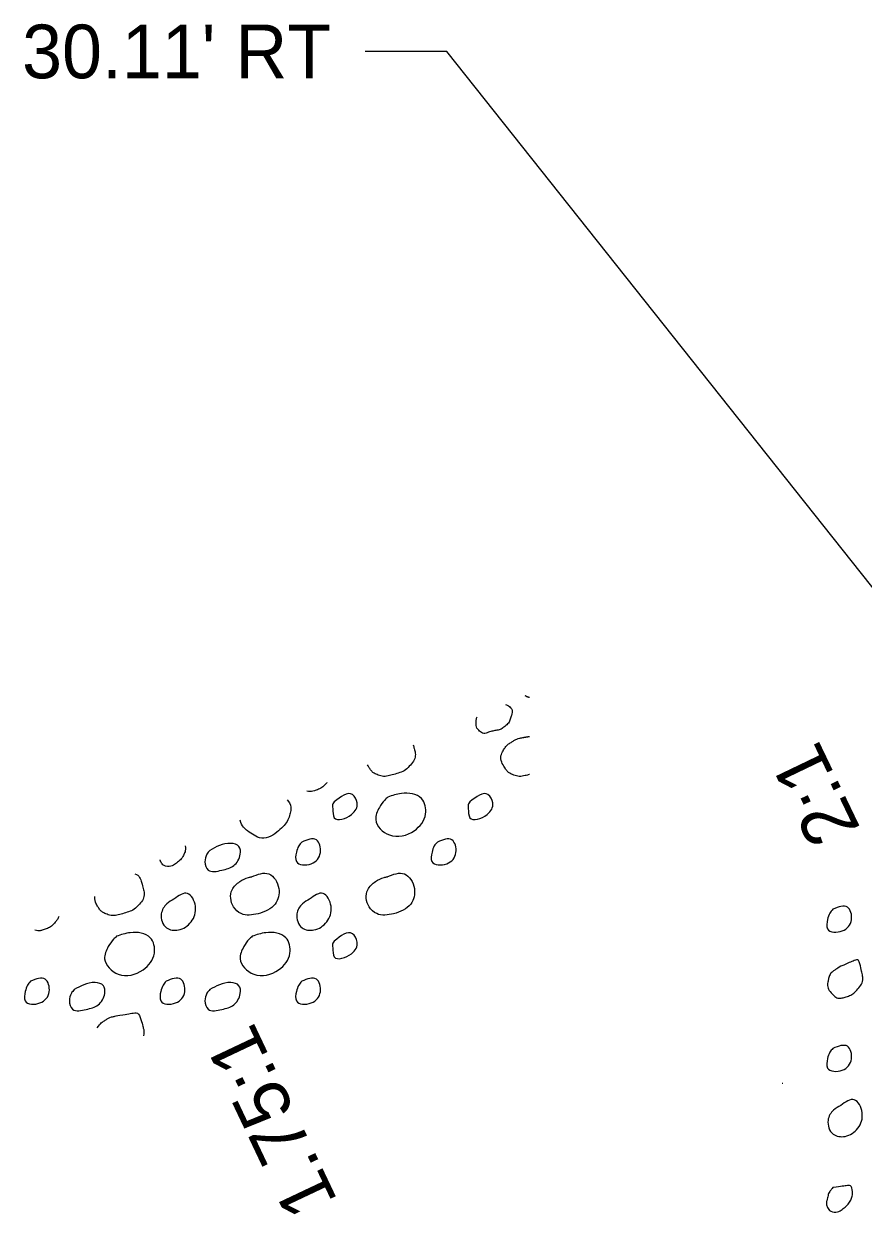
# Model space of a CAD drawing. Extents: x 0 to 2278, y -264 to 330.
# Drawn here: x 81.23 to 114.06, y 222.03 to 268.6 of the extents above; entities that cross this region are included whole.
import ezdxf

# ---------------------------------------------------------------- set-up
doc = ezdxf.new("R2010")
doc.units = 0
doc.layers.add('DR_P_Culvert', color=7, linetype='Continuous')
doc.layers.add('XS_P_Finished_Grade', color=7, linetype='Continuous')

msp = doc.modelspace()

# ---------------------------------------------------------------- linework, layer by layer
at = {"layer": 'DR_P_Culvert'}
for p, q in [((97.773, 267.515), (94.583, 267.515)), ((131.975, 224.45), (97.773, 267.515))]:
    msp.add_line(p, q, dxfattribs=at)
at = {"layer": 'XS_P_Finished_Grade'}
for points, degree in [([(101.009, 242.239), (100.95, 242.252), (100.894, 242.274), (100.84, 242.304)], 2), ([(100.066, 241.966), (100.13, 241.95), (100.192, 241.917), (100.252, 241.857), (100.343, 241.767), (100.33, 241.647), (100.303, 241.552), (100.259, 241.395), (100.2, 241.235), (100.047, 241.107), (99.897, 240.983), (99.738, 240.965), (99.577, 240.927), (99.408, 240.888), (99.215, 240.788), (99.05, 240.936), (98.941, 241.034), (98.918, 241.148), (98.921, 241.26), (98.923, 241.331), (98.93, 241.411), (98.956, 241.481)], 3), ([(96.456, 240.39), (96.476, 240.327), (96.492, 240.266), (96.506, 240.215), (96.558, 240.022), (96.524, 239.786), (96.361, 239.605), (96.161, 239.384), (95.939, 239.299), (95.692, 239.226), (95.48, 239.164), (95.243, 239.141), (95.032, 239.23), (94.904, 239.284), (94.811, 239.377), (94.734, 239.497), (94.71, 239.533), (94.69, 239.572), (94.673, 239.612)], 3), ([(101.009, 239.23), (101.005, 239.229), (101, 239.228), (100.996, 239.226), (100.784, 239.164), (100.547, 239.141), (100.336, 239.23), (100.208, 239.284), (100.115, 239.377), (100.037, 239.497), (99.908, 239.698), (99.869, 239.975), (99.982, 240.165), (100.057, 240.291), (100.159, 240.402), (100.29, 240.485), (100.4, 240.555), (100.506, 240.622), (100.628, 240.647), (100.67, 240.656), (100.711, 240.665), (100.752, 240.674)], 3), ([(100.74, 240.671), (100.829, 240.687), (100.919, 240.703), (101.009, 240.718)], 2), ([(93.085, 238.918), (93.083, 238.915), (93.08, 238.912), (93.077, 238.909), (92.928, 238.729), (92.757, 238.644), (92.577, 238.59), (92.492, 238.564), (92.393, 238.551), (92.297, 238.574)], 3), ([(91.529, 238.239), (91.682, 238.073), (91.688, 237.852), (91.64, 237.682), (91.572, 237.448), (91.424, 237.225), (91.196, 237.03), (90.911, 236.787), (90.515, 236.691), (90.224, 236.864), (89.994, 236.999), (89.753, 237.201), (89.697, 237.439)], 3), ([(87.539, 236.442), (87.554, 236.345), (87.548, 236.239), (87.525, 236.176), (87.465, 236.013), (87.318, 235.851), (87.165, 235.734), (87.008, 235.614), (86.676, 235.634), (86.585, 235.819), (86.573, 235.843), (86.565, 235.867), (86.56, 235.892)], 3), ([(85.572, 235.337), (85.756, 235.298), (85.847, 234.962), (85.899, 234.769), (85.95, 234.576), (85.917, 234.34), (85.754, 234.159), (85.554, 233.938), (85.331, 233.853), (85.085, 233.781), (84.873, 233.718), (84.636, 233.695), (84.425, 233.784), (84.297, 233.838), (84.204, 233.932), (84.126, 234.052), (84.049, 234.171), (84.004, 234.318), (84.004, 234.457)], 3), ([(82.595, 233.667), (82.566, 233.597), (82.524, 233.528), (82.47, 233.463), (82.32, 233.284), (82.15, 233.199), (81.97, 233.144), (81.874, 233.115), (81.761, 233.102), (81.655, 233.139)], 3), ([(113.183, 231.723), (113.358, 231.799), (113.534, 231.874), (113.71, 231.95), (113.892, 232.028), (113.981, 231.628), (114.021, 231.442), (114.064, 231.246), (114.013, 231.025), (113.854, 230.835), (113.704, 230.655), (113.534, 230.57), (113.354, 230.516), (113.21, 230.472), (113.029, 230.465), (112.888, 230.605), (112.717, 230.773), (112.653, 230.972), (112.688, 231.143), (112.715, 231.28), (112.779, 231.46), (112.906, 231.545), (112.998, 231.606), (113.091, 231.664), (113.183, 231.723)], 3), ([(84.098, 229.317), (84.17, 229.425), (84.263, 229.52), (84.379, 229.594), (84.489, 229.664), (84.595, 229.73), (84.717, 229.756), (84.759, 229.765), (84.8, 229.774), (84.841, 229.782)], 3), ([(84.829, 229.78), (85.055, 229.819), (85.283, 229.862), (85.51, 229.894), (85.737, 229.925), (85.842, 229.536), (85.899, 229.324), (85.925, 229.225), (85.929, 229.114), (85.905, 229.006)], 3), ([(110.888, 227.147), (110.899, 227.149), (110.91, 227.152), (110.921, 227.154)], 2), ([(112.876, 223.064), (113.067, 223.092), (113.258, 223.122), (113.449, 223.148), (113.619, 223.171), (113.659, 222.803), (113.605, 222.656), (113.546, 222.493), (113.398, 222.331), (113.245, 222.214), (113.088, 222.094), (112.756, 222.114), (112.665, 222.299), (112.608, 222.416), (112.636, 222.551), (112.669, 222.668), (112.692, 222.751), (112.702, 222.845), (112.756, 222.913), (112.796, 222.964), (112.836, 223.014), (112.876, 223.064)], 3)]:
    msp.add_open_spline(points, degree=degree, dxfattribs=at)
for points in [[(93.369, 238.155), (94.081, 238.444), (94.27, 238.116), (94.046, 237.662), (93.371, 237.536), (93.312, 237.896), (93.319, 238.077), (93.369, 238.155)], [(95.467, 238.344), (96.001, 238.484), (96.782, 238.286), (96.944, 237.682), (96.5, 237.03), (95.527, 236.864), (94.996, 237.461), (95.139, 237.939), (95.346, 238.227), (95.467, 238.344)], [(98.672, 238.155), (99.385, 238.444), (99.573, 238.116), (99.35, 237.662), (98.675, 237.536), (98.616, 237.896), (98.622, 238.077), (98.672, 238.155)], [(92.1, 236.584), (92.672, 236.668), (92.829, 236.176), (92.469, 235.734), (91.889, 235.819), (91.892, 236.188), (91.98, 236.433), (92.1, 236.584)], [(97.404, 236.584), (97.976, 236.668), (98.132, 236.176), (97.772, 235.734), (97.192, 235.819), (97.196, 236.188), (97.284, 236.433), (97.404, 236.584)], [(88.502, 236.259), (88.877, 236.447), (89.329, 236.533), (89.645, 236.412), (89.696, 236.107), (89.44, 235.662), (88.97, 235.482), (88.442, 235.491), (88.314, 235.814), (88.391, 236.114), (88.502, 236.259)], [(90.132, 235.226), (90.814, 235.339), (91.202, 234.769), (91.057, 234.159), (90.389, 233.781), (89.729, 233.784), (89.43, 234.052), (89.375, 234.719), (89.682, 235.039), (90.021, 235.202), (90.145, 235.228)], [(95.436, 235.226), (96.117, 235.339), (96.506, 234.769), (96.361, 234.159), (95.692, 233.781), (95.032, 233.784), (94.734, 234.052), (94.679, 234.719), (94.986, 235.039), (95.325, 235.202), (95.449, 235.228)], [(87.102, 234.352), (87.63, 234.578), (87.941, 234.071), (87.774, 233.463), (87.274, 233.144), (86.807, 233.233), (86.607, 233.772), (86.826, 234.173), (87.102, 234.352)], [(92.406, 234.352), (92.934, 234.578), (93.245, 234.071), (93.077, 233.463), (92.577, 233.144), (92.111, 233.233), (91.911, 233.772), (92.13, 234.173), (92.406, 234.352)], [(112.876, 233.956), (113.449, 234.04), (113.605, 233.547), (113.245, 233.106), (112.665, 233.191), (112.669, 233.56), (112.756, 233.805), (112.876, 233.956)], [(84.86, 232.898), (85.394, 233.038), (86.175, 232.841), (86.336, 232.237), (85.892, 231.584), (84.92, 231.418), (84.389, 232.016), (84.531, 232.493), (84.739, 232.782), (84.86, 232.898)], [(90.164, 232.898), (90.697, 233.038), (91.479, 232.841), (91.64, 232.237), (91.196, 231.584), (90.224, 231.418), (89.692, 232.016), (89.835, 232.493), (90.042, 232.782), (90.164, 232.898)], [(93.369, 232.709), (94.081, 232.998), (94.27, 232.671), (94.046, 232.217), (93.371, 232.091), (93.312, 232.451), (93.319, 232.632), (93.369, 232.709)], [(81.492, 231.139), (82.065, 231.222), (82.221, 230.73), (81.861, 230.289), (81.281, 230.374), (81.285, 230.742), (81.372, 230.987), (81.492, 231.139)], [(83.199, 230.814), (83.574, 231.001), (84.025, 231.087), (84.341, 230.966), (84.392, 230.661), (84.136, 230.216), (83.666, 230.036), (83.139, 230.045), (83.01, 230.369), (83.087, 230.669), (83.199, 230.814)], [(86.796, 231.139), (87.369, 231.222), (87.525, 230.73), (87.165, 230.289), (86.585, 230.374), (86.589, 230.742), (86.676, 230.987), (86.796, 231.139)], [(88.502, 230.814), (88.877, 231.001), (89.329, 231.087), (89.645, 230.966), (89.696, 230.661), (89.44, 230.216), (88.97, 230.036), (88.442, 230.045), (88.314, 230.369), (88.391, 230.669), (88.502, 230.814)], [(92.1, 231.139), (92.672, 231.222), (92.829, 230.73), (92.469, 230.289), (91.889, 230.374), (91.892, 230.742), (91.98, 230.987), (92.1, 231.139)], [(112.876, 228.51), (113.449, 228.594), (113.605, 228.101), (113.245, 227.66), (112.665, 227.745), (112.669, 228.114), (112.756, 228.359), (112.876, 228.51)], [(113.183, 226.278), (113.71, 226.504), (114.021, 225.996), (113.854, 225.389), (113.354, 225.07), (112.888, 225.159), (112.688, 225.698), (112.906, 226.099), (113.183, 226.278)]]:
    msp.add_spline(points, degree=3, dxfattribs=at)

# ---------------------------------------------------------------- texts
at = {"layer": 'DR_P_Culvert'}
msp.add_text("30.11' RT", height=2.1, dxfattribs=at).set_placement((81.162, 266.465))
for s, rotation, p in [('2:1', 115.6557, (113.972, 237.105)), ('2:1', 115.6557, (113.972, 237.105)), ('1.75:1', 115.3275, (93.522, 222.534))]:
    msp.add_text(s, height=2.1, rotation=rotation, dxfattribs=at).set_placement(p)

doc.saveas('drawing.dxf')
